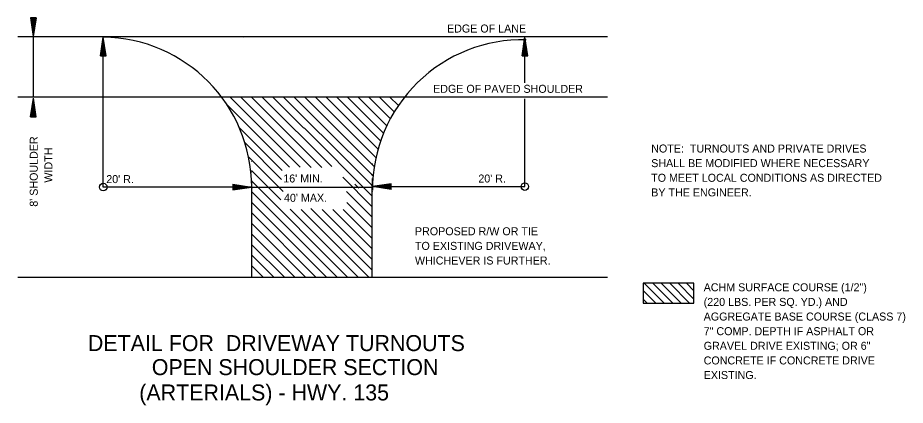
# Model space of a CAD drawing. Extents: x 1955770 to 1955917, y 566446 to 566544.
# Drawn here: x 1955770.4 to 1955836.9, y 566467 to 566496.1 of the extents above; entities that cross this region are included whole.
import ezdxf

# ---------------------------------------------------------------- set-up
doc = ezdxf.new("R2010")
doc.units = 0
doc.layers.add('Default', color=7, linetype='Continuous')

msp = doc.modelspace()

# ---------------------------------------------------------------- linework, layer by layer
at = {"layer": 'Default'}
for p, q in [((1955771.349, 566496.114), (1955771.561, 566494.699)), ((1955771.774, 566496.114), (1955771.349, 566496.114)), ((1955771.382, 566496.114), (1955771.561, 566494.935)), ((1955771.422, 566496.114), (1955771.561, 566495.177)), ((1955771.458, 566496.114), (1955771.561, 566495.413)), ((1955771.492, 566496.114), (1955771.561, 566495.654)), ((1955771.528, 566496.114), (1955771.561, 566495.885)), ((1955771.774, 566496.114), (1955771.561, 566494.699)), ((1955771.627, 566496.114), (1955771.561, 566495.654)), ((1955771.704, 566496.114), (1955771.561, 566495.177)), ((1955771.74, 566496.114), (1955771.561, 566494.935)), ((1955771.665, 566496.114), (1955771.561, 566495.413)), ((1955771.595, 566496.114), (1955771.561, 566495.885)), ((1955770.397, 566494.699), (1955814.601, 566494.699)), ((1955771.567, 566490.181), (1955771.567, 566494.699)), ((1955776.596, 566493.251), (1955776.809, 566494.663)), ((1955776.629, 566493.251), (1955776.809, 566494.425)), ((1955777.018, 566493.251), (1955776.809, 566494.663)), ((1955776.809, 566483.41), (1955776.809, 566494.663)), ((1955776.984, 566493.251), (1955776.809, 566494.425)), ((1955787.319, 566494.652), (1955787.339, 566494.714)), ((1955787.339, 566494.694), (1955787.319, 566494.652)), ((1955787.319, 566494.652), (1955787.339, 566494.672)), ((1955808.2, 566493.257), (1955808.413, 566494.672)), ((1955808.234, 566493.257), (1955808.413, 566494.43)), ((1955808.625, 566493.257), (1955808.413, 566494.672)), ((1955808.413, 566491.238), (1955808.413, 566494.672)), ((1955808.588, 566493.257), (1955808.413, 566494.43)), ((1955776.665, 566493.251), (1955776.809, 566494.182)), ((1955776.701, 566493.251), (1955776.809, 566493.95)), ((1955776.741, 566493.251), (1955776.809, 566493.709)), ((1955776.949, 566493.251), (1955776.809, 566494.182)), ((1955776.911, 566493.251), (1955776.809, 566493.95)), ((1955776.877, 566493.251), (1955776.809, 566493.709)), ((1955808.27, 566493.257), (1955808.413, 566494.19)), ((1955808.306, 566493.257), (1955808.413, 566493.955)), ((1955808.342, 566493.257), (1955808.413, 566493.714)), ((1955808.552, 566493.257), (1955808.413, 566494.19)), ((1955808.517, 566493.257), (1955808.413, 566493.955)), ((1955808.482, 566493.257), (1955808.413, 566493.714)), ((1955776.596, 566493.251), (1955777.018, 566493.251)), ((1955776.773, 566493.251), (1955776.809, 566493.473)), ((1955776.842, 566493.251), (1955776.809, 566493.473)), ((1955808.2, 566493.257), (1955808.625, 566493.257)), ((1955808.377, 566493.257), (1955808.413, 566493.479)), ((1955808.446, 566493.257), (1955808.413, 566493.479)), ((1955770.397, 566490.181), (1955814.601, 566490.181)), ((1955771.359, 566488.676), (1955771.57, 566490.091)), ((1955771.394, 566488.676), (1955771.57, 566489.85)), ((1955771.783, 566488.676), (1955771.57, 566490.091)), ((1955771.746, 566488.676), (1955771.57, 566489.85)), ((1955808.413, 566483.441), (1955808.413, 566490.026)), ((1955771.43, 566488.676), (1955771.57, 566489.61)), ((1955771.464, 566488.676), (1955771.57, 566489.375)), ((1955771.502, 566488.676), (1955771.57, 566489.133)), ((1955771.713, 566488.676), (1955771.57, 566489.61)), ((1955771.673, 566488.676), (1955771.57, 566489.375)), ((1955771.639, 566488.676), (1955771.57, 566489.133)), ((1955771.359, 566488.676), (1955771.783, 566488.676)), ((1955771.537, 566488.676), (1955771.57, 566488.899)), ((1955771.604, 566488.676), (1955771.57, 566488.899)), ((1955791.864, 566487.846), (1955796.968, 566482.726)), ((1955793.453, 566487.838), (1955797.034, 566484.246)), ((1955787.421, 566486.754), (1955790.181, 566483.984)), ((1955795.653, 566486.423), (1955797.122, 566484.95)), ((1955787.7, 566485.681), (1955790.304, 566483.07)), ((1955788.695, 566486.178), (1955790.217, 566484.652)), ((1955787.93, 566484.659), (1955790.122, 566482.459)), ((1955795.888, 566484.602), (1955796.968, 566483.518)), ((1955787.93, 566483.908), (1955787.93, 566483.38)), ((1955787.93, 566483.867), (1955795.124, 566476.65)), ((1955794.766, 566484.143), (1955796.968, 566481.934)), ((1955796.968, 566484.061), (1955796.968, 566483.416)), ((1955798.398, 566483.653), (1955796.987, 566483.441)), ((1955798.398, 566483.232), (1955798.398, 566483.653)), ((1955787.93, 566483.41), (1955776.809, 566483.41)), ((1955786.518, 566483.62), (1955787.93, 566483.41)), ((1955786.518, 566483.62), (1955786.518, 566483.196)), ((1955786.518, 566483.587), (1955787.691, 566483.41)), ((1955786.518, 566483.55), (1955787.451, 566483.41)), ((1955786.518, 566483.51), (1955787.215, 566483.41)), ((1955786.518, 566483.479), (1955786.975, 566483.41)), ((1955786.518, 566483.443), (1955786.739, 566483.41)), ((1955786.518, 566483.196), (1955787.93, 566483.41)), ((1955786.518, 566483.339), (1955786.975, 566483.41)), ((1955786.518, 566483.268), (1955787.451, 566483.41)), ((1955786.518, 566483.229), (1955787.691, 566483.41)), ((1955786.518, 566483.303), (1955787.215, 566483.41)), ((1955786.518, 566483.375), (1955786.739, 566483.41)), ((1955787.93, 566483.41), (1955787.93, 566476.65)), ((1955787.93, 566483.41), (1955795.898, 566483.41)), ((1955787.93, 566483.074), (1955794.332, 566476.65)), ((1955795.04, 566483.074), (1955796.968, 566481.142)), ((1955795.676, 566483.41), (1955797.019, 566483.41)), ((1955796.968, 566476.639), (1955796.968, 566483.441)), ((1955798.398, 566483.232), (1955796.987, 566483.441)), ((1955796.987, 566483.441), (1955808.413, 566483.441)), ((1955798.398, 566483.62), (1955797.223, 566483.441)), ((1955798.398, 566483.265), (1955797.223, 566483.441)), ((1955798.398, 566483.584), (1955797.467, 566483.441)), ((1955798.398, 566483.301), (1955797.467, 566483.441)), ((1955798.398, 566483.548), (1955797.699, 566483.441)), ((1955798.398, 566483.339), (1955797.699, 566483.441)), ((1955798.398, 566483.514), (1955797.94, 566483.441)), ((1955798.398, 566483.374), (1955797.94, 566483.441)), ((1955798.398, 566483.474), (1955798.174, 566483.441)), ((1955798.398, 566483.407), (1955798.174, 566483.441)), ((1955787.93, 566482.28), (1955793.542, 566476.65)), ((1955790.824, 566481.755), (1955795.912, 566476.65)), ((1955791.646, 566481.723), (1955796.704, 566476.65)), ((1955792.362, 566481.799), (1955796.968, 566477.178)), ((1955793.213, 566481.735), (1955796.968, 566477.97)), ((1955794.005, 566481.733), (1955796.968, 566478.764)), ((1955794.798, 566481.733), (1955796.968, 566479.556)), ((1955795.071, 566482.252), (1955796.968, 566480.348)), ((1955787.93, 566481.488), (1955792.752, 566476.65)), ((1955787.93, 566480.695), (1955791.96, 566476.65)), ((1955787.93, 566479.901), (1955791.172, 566476.65)), ((1955787.93, 566479.109), (1955790.382, 566476.65)), ((1955787.93, 566478.316), (1955789.59, 566476.65)), ((1955787.93, 566477.524), (1955788.802, 566476.65)), ((1955770.397, 566476.65), (1955814.601, 566476.65))]:
    msp.add_line(p, q, dxfattribs=at)
for points in [[(1955786.058, 566489.621), (1955790.776, 566484.899)], [(1955786.298, 566490.181), (1955791.58, 566484.895)], [(1955787.095, 566490.181), (1955792.402, 566484.879)], [(1955787.894, 566490.181), (1955793.204, 566484.871)], [(1955788.69, 566490.181), (1955793.932, 566484.942)], [(1955789.49, 566490.181), (1955791.843, 566487.826)], [(1955790.284, 566490.181), (1955795.882, 566484.596)], [(1955791.084, 566490.181), (1955793.441, 566487.826)], [(1955791.892, 566490.181), (1955795.653, 566486.423)], [(1955792.685, 566490.181), (1955795.046, 566487.826)], [(1955793.483, 566490.181), (1955797.408, 566486.258)], [(1955794.28, 566490.181), (1955797.599, 566486.865)], [(1955795.079, 566490.181), (1955797.819, 566487.452)], [(1955795.882, 566490.181), (1955798.062, 566488.005)], [(1955796.682, 566490.181), (1955798.33, 566488.533)], [(1955797.484, 566490.181), (1955798.62, 566489.044)], [(1955798.276, 566490.181), (1955798.931, 566489.526)], [(1955787.005, 566487.876), (1955788.695, 566486.178)], [(1955795.044, 566487.826), (1955797.247, 566485.616)], [(1955787.93, 566485.353), (1955787.952, 566485.331)], [(1955796.907, 566485.165), (1955796.968, 566485.104)], [(1955787.93, 566484.554), (1955787.946, 566484.531)], [(1955796.909, 566484.356), (1955797.001, 566484.267)], [(1955787.924, 566483.76), (1955787.943, 566483.739)], [(1955795.676, 566483.631), (1955795.966, 566483.337)], [(1955787.943, 566483.372), (1955788, 566483.315)], [(1955796.911, 566483.556), (1955796.968, 566483.502)], [(1955796.947, 566483.154), (1955797.014, 566483.091)], [(1955817.368, 566476.191), (1955818.862, 566474.697)], [(1955818.001, 566476.191), (1955819.495, 566474.697)], [(1955818.633, 566476.191), (1955820.127, 566474.697)], [(1955819.268, 566476.191), (1955820.762, 566474.697)], [(1955819.903, 566476.191), (1955821.09, 566475.001)], [(1955820.535, 566476.191), (1955821.09, 566475.632)], [(1955817.28, 566475.643), (1955818.229, 566474.697)], [(1955817.28, 566475.008), (1955817.593, 566474.697)]]:
    msp.add_lwpolyline(points, dxfattribs=at)
msp.add_lwpolyline([(1955817.28, 566476.191), (1955817.28, 566474.697), (1955821.09, 566474.697), (1955821.09, 566476.191)], close=True, dxfattribs=at)
for centre in [(1955776.808, 566483.41), (1955808.412, 566483.441)]:
    msp.add_circle(centre, 0.282, dxfattribs=at)
for centre, radius, start, end in [((1955776.665, 566483.395), 11.268, 0.07639, 89.27429), ((1955808.257, 566483.196), 11.273, 88.75379, 180)]:
    msp.add_arc(centre, radius, start, end, dxfattribs=at)

# ---------------------------------------------------------------- texts
for s, height, p in [('EDGE OF LANE', 0.6, (1955802.577, 566495.003)), ('EDGE OF PAVED SHOULDER', 0.6, (1955801.532, 566490.479)), ('NOTE:  TURNOUTS AND PRIVATE DRIVES', 0.6, (1955817.883, 566486)), ('SHALL BE MODIFIED WHERE NECESSARY', 0.6, (1955817.883, 566484.903)), ("20' R.", 0.6, (1955777.033, 566483.705)), ("16' MIN.", 0.6, (1955790.302, 566483.752)), ("20' R.", 0.6, (1955804.925, 566483.75)), ('TO MEET LOCAL CONDITIONS AS DIRECTED', 0.6, (1955817.883, 566483.805)), ('BY THE ENGINEER.', 0.6, (1955817.883, 566482.708)), ("40' MAX.", 0.6, (1955790.356, 566482.303)), ('PROPOSED R/W OR TIE', 0.6, (1955800.173, 566479.792)), ('TO EXISTING DRIVEWAY,', 0.6, (1955800.173, 566478.695)), ('WHICHEVER IS FURTHER.', 0.6, (1955800.173, 566477.597)), ('ACHM SURFACE COURSE (1/2") ', 0.6, (1955821.818, 566475.588)), ('(220 LBS. PER SQ. YD.) AND ', 0.6, (1955821.818, 566474.49)), ('AGGREGATE BASE COURSE (CLASS 7)', 0.6, (1955821.818, 566473.393)), ('7" COMP. DEPTH IF ASPHALT OR', 0.6, (1955821.818, 566472.295)), ('DETAIL FOR  DRIVEWAY TURNOUTS', 1.2, (1955775.653, 566471.101)), ('GRAVEL DRIVE EXISTING; OR 6"', 0.6, (1955821.818, 566471.198)), ('OPEN SHOULDER SECTION', 1.2, (1955780.445, 566469.298)), ('CONCRETE IF CONCRETE DRIVE', 0.6, (1955821.818, 566470.1)), ('EXISTING.', 0.6, (1955821.818, 566469.003)), ('(ARTERIALS) - HWY. 135', 1.2, (1955779.505, 566467.397))]:
    msp.add_text(s, height=height, dxfattribs=at).set_placement(p)
for s, p in [("8' SHOULDER", (1955771.897, 566481.934)), ('WIDTH', (1955772.994, 566483.741))]:
    msp.add_text(s, height=0.6, rotation=90, dxfattribs=at).set_placement(p)

doc.saveas('drawing.dxf')
